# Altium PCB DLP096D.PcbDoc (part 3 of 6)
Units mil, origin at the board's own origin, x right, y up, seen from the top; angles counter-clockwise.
Board outline 4950 x 3159.45 mil, 8 copper layers (Top Layer, GND1, SIGNAL1, POWER1, POWER2, SIGNAL2, GND2, Bottom Layer), stack 60.4 mil thick; 328 components, 223 nets, 1380 pads, 856 vias.
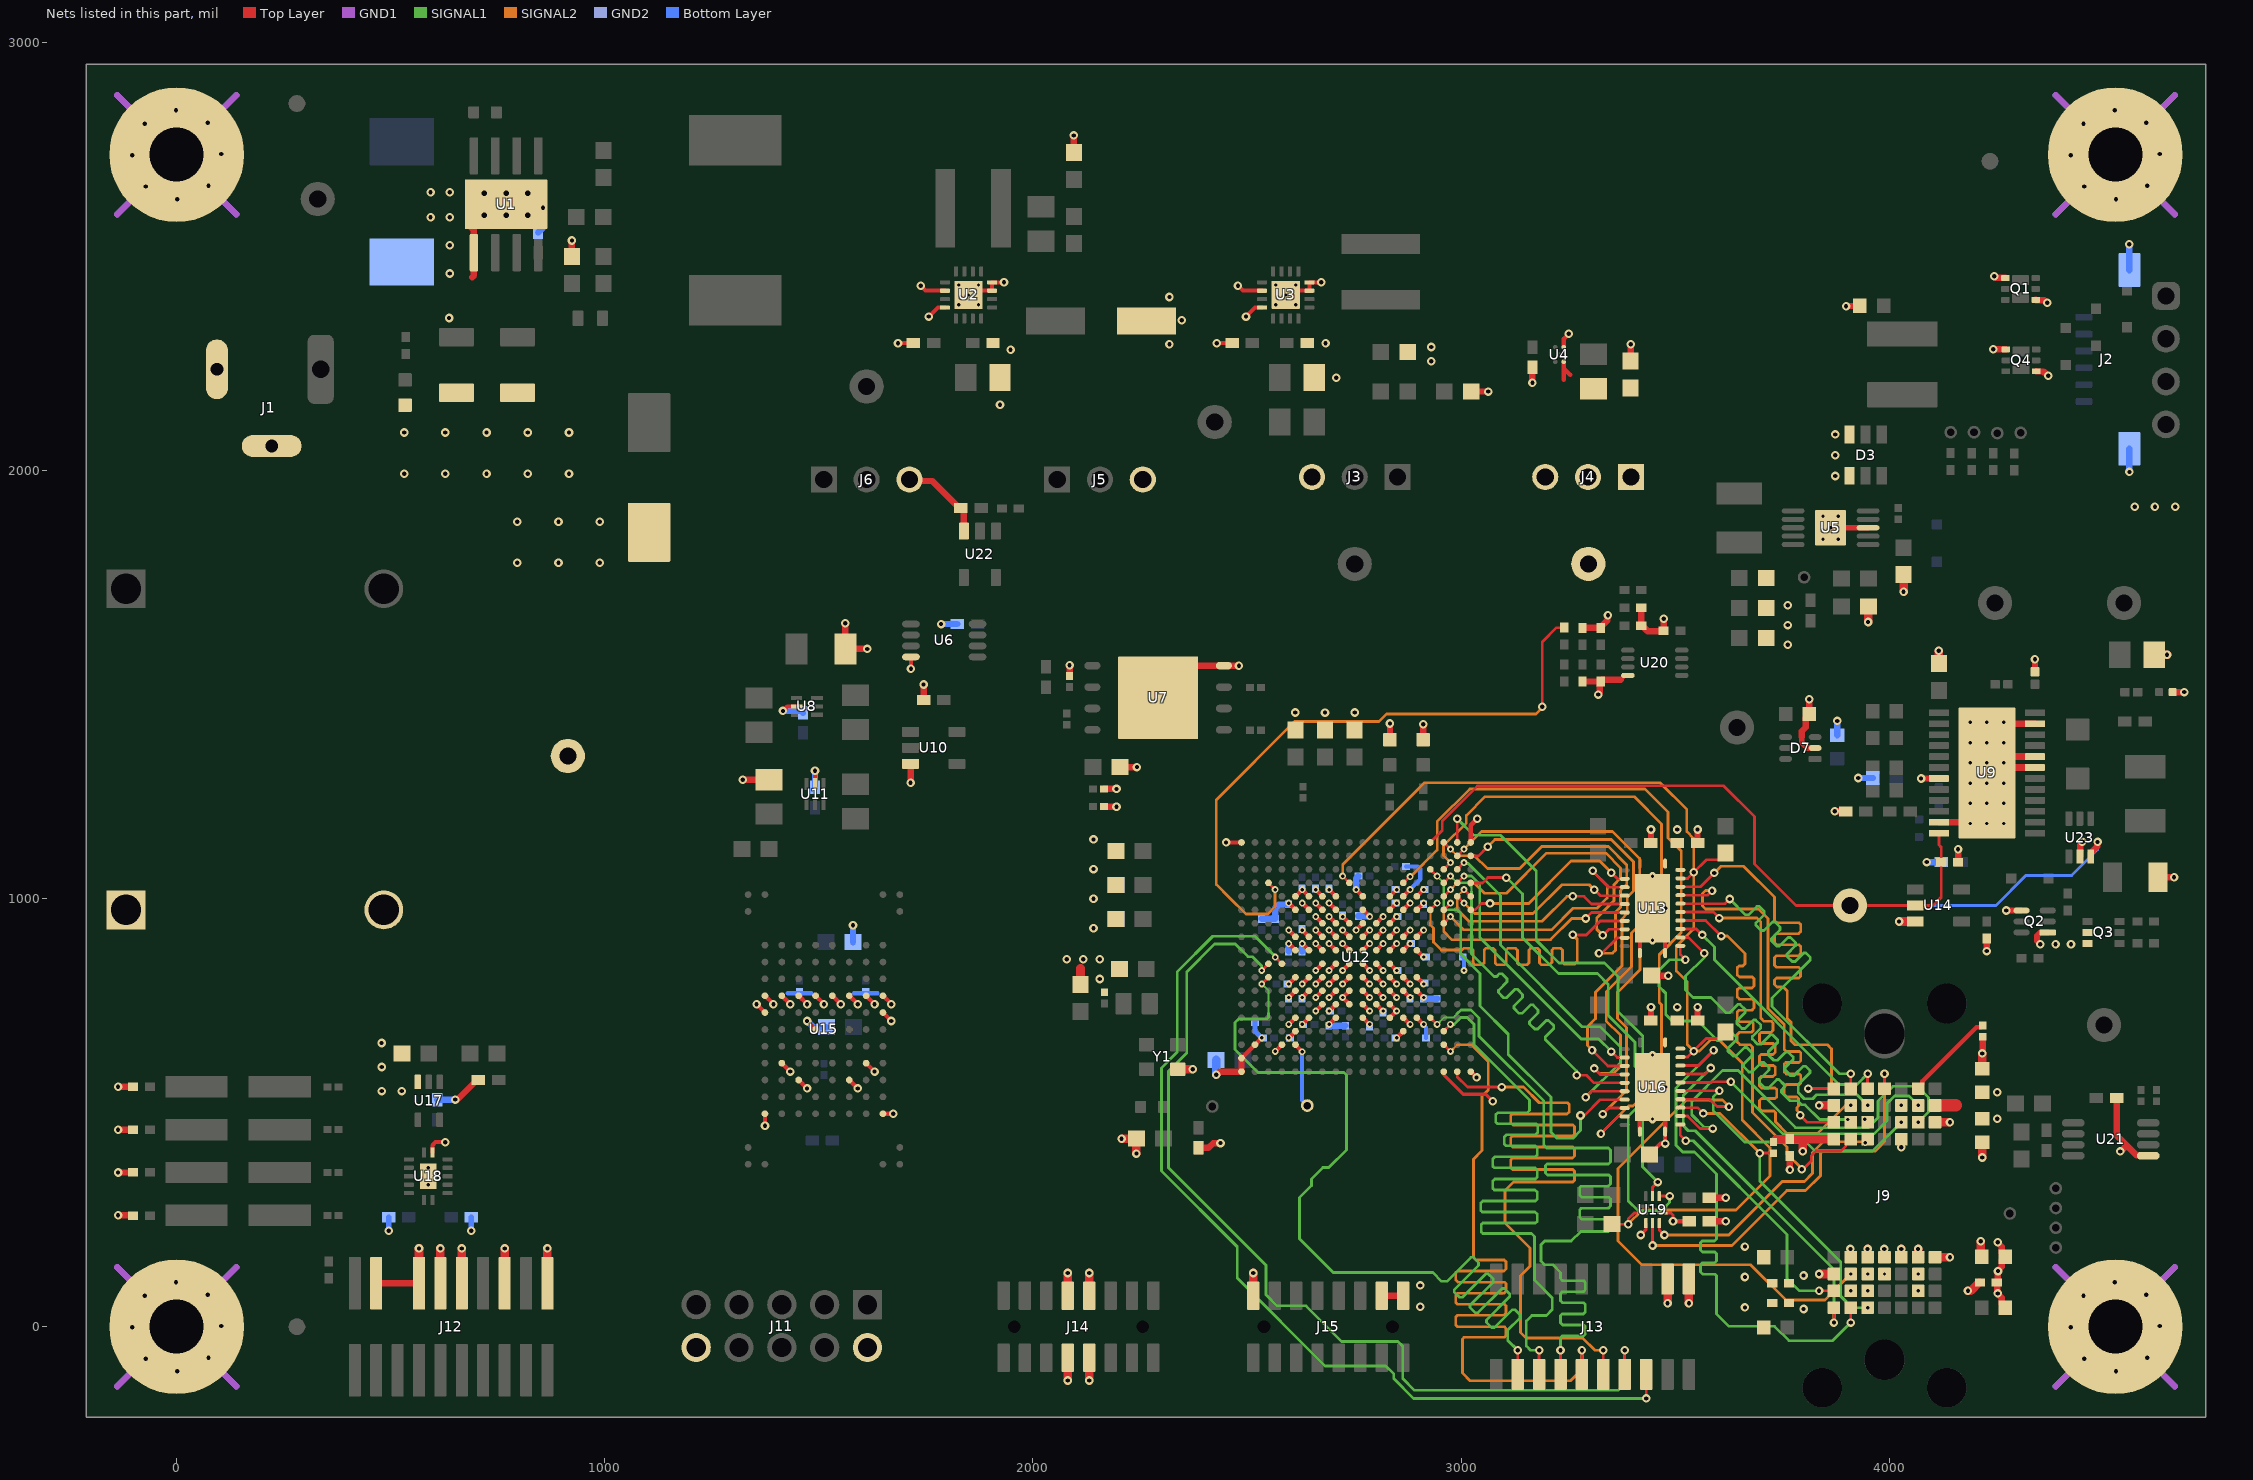
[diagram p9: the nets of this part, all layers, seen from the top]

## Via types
v1: diameter 20, hole 10, Top Layer to Bottom Layer, tented top, 596 vias
v2: diameter 16, hole 8, Top Layer to Bottom Layer, tented both sides, 126 vias
v3: diameter 16, hole 8.01, Top Layer to Bottom Layer, tented top, 63 vias
v4: diameter 19.68, hole 7.87, Top Layer to Bottom Layer, 37 vias
v5: diameter 16, hole 8.02, Top Layer to Bottom Layer, tented bottom, 22 vias
v6: diameter 24.8, hole 12.99, Top Layer to Bottom Layer, 6 vias
v7: diameter 19.68, hole 7.87, Top Layer to Bottom Layer, tented both sides, 6 vias

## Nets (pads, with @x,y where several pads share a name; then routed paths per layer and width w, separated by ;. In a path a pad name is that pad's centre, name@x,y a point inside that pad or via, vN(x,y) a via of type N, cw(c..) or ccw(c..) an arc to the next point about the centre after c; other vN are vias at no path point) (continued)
DAC_OUT: TP23.1 U12.T5 | length 153.6
  Top Layer w6.5: U12.T5@2613.07,658.27 U12.T5@2613.07,658.72 ; v3(2628.55,642.35) v3@2628.55,642.8
  Top Layer w10: U12.T5@2613.07,658.27 v3@2628.55,642.8
  Bottom Layer w10: v3(2628.55,642.35) 2628.55,528.65 TP23.1@2640.68,516.52
DMD_1V8: C42.2 C50.2 C52.1 C53.1 C55.1 C57.2 C58.1 C60.1 C61.1 C62.1 J4.2 J9.A5 J9.B12 J9.C14 J9.D12 J9.F13 J9.G3 R65.2 TP7.1 U13.23 U13.24 U16.23 U16.24 U19.6 | length 417.8
  Top Layer w7: U19.6@3470.73,265.67 3490.4,265.67 3494.93,261.15 v1(3494.93,246.28)
  Top Layer w10: v1(3494.93,246.28) C57.2@3532.29,246.28 ; v1@3909.25,184.4 3909.7,183.95 3909.7,162.92 J9.B12@3910.15,162.48 ; v1@3988.59,184.55 3988.74,184.4 3988.74,162.62 J9.D12@3988.89,162.48
  Top Layer w19.68: R65.2@3729.99,432.16 3735.9,438.07 C55.1@3767.94,438.07 3794.97,438.07 ; v1(3797.71,409.67) v1(3797.71,409.67) 3797.65,435.38 3794.97,438.07 ; J9.A5@3871.02,438.07 J9.A5@3870.78,438.07 3794.97,438.07 ; v1(4183.78,84.03) 4183.84,84.09 4190.74,84.09 4209.83,103.18 C60.1@4211.8,103.18 ; v1(4213.99,199.64) 4214.05,199.58 4214.05,164.73 C58.1@4215.74,163.04
  Top Layer w29: J9.G3@4107,516.81 4155.75,516.81
  other v1: 3799.96,41.32 3799.96,119.53 3909.25,181.73 3988.59,181.73 4252.41,485.92 4252.41,547.57 3504.97,746.65 3504.97,1161.3
  other v5: 3949.52,83.74 4067.63,123.11
DMD_1V8_OB: C12.1 J4.1 L5.2 U4.C3 | length 63
  Top Layer w10: 3239.65,2212.06 3239.65,2238.27 ; U4.C3@3239.65,2253.67 3239.65,2238.27 ; 3254.78,2223.14 3239.65,2238.27
DMD_D0: U12.F18 U13.3 | length 423.8
  Top Layer w6.5: U12.F18@3022.52,973.68 3032.3,973.68 3047.17,988.55 v1(3067.46,988.55) ; v1(3350.94,1060.17) 3364.93,1046.19 U13.3@3382.11,1046.19
  SIGNAL2 w6.5: v1(3067.46,988.55) 3073.74,988.55 3158.08,988.55 3256.96,1087.43 3323.69,1087.43 v1(3350.94,1060.17)
DMD_D0_1v8: J9.A2 U13.21 | length 1267.1
  Top Layer w6.5: U13.21@3512.03,1027.49 3558.88,1027.49 v1(3591.2,1059.81) ; v1(3811.01,556.18) J9.A2@3870.78,556.18
  SIGNAL2 w6.5: v1(3591.2,1059.81) 3606.95,1075.56 3659.95,1075.56 3732.17,1003.34 3732.17,948.49 3737.16,943.49 3789.25,943.49 3793.06,939.69 3793.06,922.71 3788.07,917.72 3735.98,917.72 3732.17,913.92 3732.17,896.94 3737.16,891.95 3789.25,891.95 3793.06,888.14 3793.06,871.17 3788.07,866.18 3735.98,866.18 3732.17,862.37 3732.17,844.35 3737.16,839.36 3788.75,839.36 3792.56,835.55 3792.56,818.57 3788.75,814.77 3737.16,814.77 3732.17,809.78 3732.17,799.64 3738.23,793.58 3752.38,793.58 3761.73,784.24 3761.73,720.15 3770.29,711.59 3770.29,667.91 3779.58,658.61 3855.35,658.61 3864.95,649.01 3864.95,564.41 3856.72,556.18 v1(3811.01,556.18)
DMD_D1: U12.G16 U13.4 | length 599.9
  Top Layer w6.5: U12.G16@2959.53,942.18 v2(2975.27,957.93) ; v1@3306.94,1064.49 3344.93,1026.5 U13.4@3382.11,1026.5
  SIGNAL2 w6.5: v2(2975.27,957.93) 3006.19,927.01 3210.71,927.01 3261.16,977.47 3317.1,977.47 3341.18,1001.55 3341.18,1030.25 v1@3306.94,1064.49
  other v1: 3307.16,1064.71
DMD_D1_1v8: J9.A4 U13.20 | length 1026.5
  Top Layer w6.5: U13.20@3512.03,1007.8 3575.47,1007.8 v1(3586.18,1018.51) ; v1(3791.81,493.73) 3808.1,477.44 3811.01,477.44 J9.A4@3870.78,477.44
  SIGNAL2 w6.5: v1(3586.18,1018.51) 3570.52,1018.51 3563.75,1011.73 3563.75,982.38 3570.55,975.57 3694.54,975.57 3716.49,953.63 3716.49,743.56 3754.63,705.42 3754.63,647.73 3759.62,642.74 3789.71,642.74 3793.51,638.94 3793.51,621.96 3788.52,616.97 3758.44,616.97 3754.63,613.16 3754.63,595.14 3759.62,590.15 3789.71,590.15 3793.51,586.34 3793.51,569.37 3789.71,565.56 3759.62,565.56 3754.63,560.57 3754.63,542.54 3760.73,536.44 3784.28,536.44 3788.09,532.64 3788.09,515.66 3784.28,511.86 3784.28,504.92 3791.81,497.38 v1(3791.81,493.73)
DMD_D2: U12.E17 U13.5 | length 446.3
  Top Layer w6.5: U12.E17@2991.02,1005.17 v2(3006.77,989.43) ; v1(3310.94,1020.8) 3324.93,1006.82 U13.5@3382.11,1006.82
  SIGNAL2 w6.5: v2(3006.77,989.43) 3031.29,964.91 3167.95,964.91 3235.41,1032.37 3299.38,1032.37 v1(3310.94,1020.8)
DMD_D2_1v8: J9.B2 U13.19 | length 1006.7
  Top Layer w6.5: U13.19@3512.03,988.12 3616.65,988.12 v1(3627.55,999.01) ; J9.B2@3910.15,556.18 v1(3910.15,590.94)
  SIGNAL1 w6.5: v1(3627.55,999.01) 3664.54,962.02 3671.02,962.02 3690.88,981.88 3696.27,981.88 3708.27,969.88 3708.27,962.82 3688.41,942.96 3688.41,937.57 3700.41,925.57 3707.47,925.57 3727.33,945.43 3732.71,945.43 3744.71,933.43 3744.71,926.37 3724.85,906.51 3724.85,901.13 3736.86,889.12 3743.91,889.12 3763.77,908.98 3769.16,908.98 3781.16,896.98 3781.16,889.93 3761.3,870.06 3761.3,864.68 3773.3,852.68 3780.36,852.68 3800.22,872.54 3805.61,872.54 3815.7,862.45 3815.7,857.06 3726.21,767.57 3726.21,748.34 3883.6,590.94 v1(3910.15,590.94)
DMD_D3: U12.E18 U13.6 | length 509.3
  Top Layer w6.5: v2(3006.77,1020.92) U12.E18@3022.52,1005.17 ; v1(3260.97,1005.15) 3286.91,1005.15 3304.93,987.13 U13.6@3382.11,987.13
  SIGNAL2 w5: 2994.72,970.45 2991.05,974.12 2991.05,1005.21 v2(3006.77,1020.92)
  SIGNAL2 w6.5: 2994.72,970.45 3018.06,947.11 3189.25,947.11 3247.29,1005.15 v1(3260.97,1005.15)
DMD_D3_1v8: J9.B3 U13.18 | length 1156.6
  Top Layer w6.5: U13.18@3512.03,968.43 3589.21,968.43 v1(3603.19,954.45)
  SIGNAL2 w6.5: v1(3603.19,954.45) 3691.01,954.45 3700.08,945.38 3700.08,720.51 3707.4,713.19 3724.72,713.19 3728.53,709.39 3728.53,692.41 3723.54,687.42 3700.45,687.42 3696.64,683.61 3696.64,666.64 3701.64,661.65 3729.72,661.65 3733.53,657.84 3733.53,640.87 3728.54,635.88 3700.45,635.88 3696.64,632.07 3696.64,615.1 3701.64,610.11 3729.72,610.11 3733.53,606.3 3733.53,589.33 3728.54,584.33 3700.45,584.33 3696.64,580.53 3696.64,562.5 3701.64,557.51 3733.22,557.51 3737.03,553.7 3737.03,536.73 3733.22,532.92 3701.64,532.92 3696.64,527.93 3696.64,509.91 3702.74,503.81 3730.29,503.81 3734.1,500 3734.1,478.68 3761.51,451.27 3832.47,451.27 3898,516.81 v5(3910.15,516.81)
DMD_D4: U12.F16 U13.7 | length 552.2
  Top Layer w6.5: U12.F16@2959.53,973.68 v2(2975.27,989.43) ; v1(3290.94,953.47) 3304.93,967.45 U13.7@3382.11,967.45
  SIGNAL2 w5: 2959.6,953.66 2959.6,973.75 v2(2975.27,989.43)
  SIGNAL2 w6.5: 2959.6,953.66 2959.6,922.37 2977.93,904.04 3208.87,904.04 3258.29,953.47 v1(3290.94,953.47)
DMD_D4_1v8: J9.B5 U13.17 | length 1128.7
  Top Layer w6.5: U13.17@3512.03,948.75 3571.16,948.75 v1(3607.59,912.32) ; v1(3795.87,367.65) 3798.11,367.65 3817.95,387.49 3817.95,399.38 3829.18,410.61 3887.45,410.61 3898.63,421.79 3898.63,426.55 J9.B5@3910.15,438.07
  SIGNAL2 w6.5: v1(3607.59,912.32) 3607.68,912.23 3622.44,912.23 3663.2,871.46 3663.2,847.83 3657.7,842.33 3648.78,842.33 3644.97,838.52 3644.97,821.55 3649.96,816.56 3680.05,816.56 3683.86,812.75 3683.86,795.78 3678.87,790.79 3648.78,790.79 3644.97,786.98 3644.97,770.01 3649.96,765.02 3680.05,765.02 3683.86,761.21 3683.86,744.23 3678.87,739.24 3648.78,739.24 3644.97,735.44 3644.97,717.41 3649.96,712.42 3678.55,712.42 3682.36,708.61 3682.36,691.64 3678.55,687.83 3649.96,687.83 3644.97,682.84 3644.97,664.81 3651.07,658.72 3674.62,658.72 3680.51,652.83 3680.51,500.47 3761.26,419.72 3761.26,403.44 3795.87,368.83 v1(3795.87,367.65)
DMD_D5: U12.F15 U13.8 | length 972.8
  Top Layer w6.5: U12.F15@2928.03,973.68 v2(2943.78,989.43) ; v1(3260.97,915.15) 3292.31,915.15 3324.93,947.76 U13.8@3382.11,947.76
  SIGNAL2 w5: 2928.1,944.54 2928.1,973.75 v2(2943.78,989.43)
  SIGNAL2 w6.5: 2928.1,944.54 2928.1,938.57 2935.3,931.37 2935.3,898.18 2953.79,879.69 3001.99,879.69 3006.4,884.11 3023.37,884.11 3028.36,879.11 3028.36,849.03 3032.17,845.22 3049.15,845.22 3054.14,850.21 3054.14,880.3 3057.94,884.11 3074.92,884.11 3079.91,879.11 3079.91,849.03 3083.72,845.22 3100.69,845.22 3105.68,850.21 3105.68,880.3 3109.49,884.11 3126.46,884.11 3131.45,879.11 3131.45,849.03 3135.26,845.22 3153.28,845.22 3158.28,850.21 3158.28,879.9 3162.08,883.71 3179.06,883.71 3182.86,879.9 3182.86,850.21 3187.86,845.22 3205.88,845.22 3211.98,851.32 3211.98,879.9 3215.79,883.71 3232.76,883.71 3236.57,879.9 3236.57,851.32 3241.56,846.33 3265.17,846.33 3271.17,852.32 3271.17,904.95 v1(3260.97,915.15)
DMD_D5_1v8: J9.C2 U13.16 | length 650.3
  Top Layer w6.5: U13.16@3512.03,929.06 3549.21,929.06 v1(3563.19,915.08) ; J9.C2@3949.52,556.18 v1(3949.52,590.94)
  SIGNAL1 w6.5: v1(3563.19,915.08) 3591.78,886.49 3591.78,857.05 3882.91,565.91 3924.49,565.91 v1(3949.52,590.94)
DMD_D6: U12.E16 U13.9 | length 732.7
  Top Layer w6.5: U12.E16@2959.53,1005.17 v2(2975.27,1020.92) ; v1(3330.94,914.1) 3344.93,928.08 U13.9@3382.11,928.08
  SIGNAL2 w5: v2(2975.27,1020.92) 2991.06,1036.71 3016.27,1036.71
  SIGNAL2 w6.5: 3016.27,1036.71 3030.34,1036.71 3054.73,1012.33 3054.79,1012.33 3105.91,1012.33 3199.6,1106.01 3338.16,1106.01 3372.53,1071.64 3372.53,1047.94 3356.92,1032.33 3356.92,994.95 3316.7,954.73 3316.7,928.34 v1(3330.94,914.1)
DMD_D6_1v8: J9.C3 U13.15 | length 1065.3
  Top Layer w6.5: U13.15@3512.03,909.38 3530.77,909.38 v1(3568.07,872.07)
  SIGNAL1 w6.5: v1(3568.07,872.07) 3568.07,862.76 3524.06,818.74 3524.06,786.17 3541.53,768.7 3583.7,768.7 3619.27,733.13 3626.32,733.13 3646.19,752.99 3651.57,752.99 3663.57,740.99 3663.57,733.93 3643.71,714.07 3643.71,708.69 3655.71,696.69 3662.77,696.69 3682.63,716.55 3688.02,716.55 3700.02,704.55 3700.02,697.49 3680.16,677.63 3680.16,672.24 3692.9,659.5 3699.96,659.5 3722.3,681.83 3727.68,681.83 3739.68,669.83 3739.68,664.45 3717.35,642.11 3717.35,635.05 3730.09,622.3 3738.72,622.3 3758.2,641.79 3763.59,641.79 3775.59,629.78 3775.59,624.4 3757.12,605.94 3757.12,598.88 3769.87,586.13 3776.93,586.13 3799.26,608.47 3804.65,608.47 3814.65,598.47 3814.65,593.08 3787.47,565.91 3787.47,546.64 3801.55,532.56 3821.31,532.56 3830.43,541.68 3924.64,541.68 v5(3949.52,516.81)
DMD_D7: U12.A16 U13.10 | length 818.9
  Top Layer w6.5: U12.A16@2959.53,1131.16 v2(2975.27,1115.41) ; v1(3321.82,872.43) 3328.96,872.43 3364.93,908.39 U13.10@3382.11,908.39
  SIGNAL2 w5: v2(2975.27,1115.41) 2990.82,1099.86 3014.15,1099.86
  SIGNAL2 w6.5: 3014.15,1099.86 3031.5,1099.86 3061.34,1070.02 3137.01,1070.02 3188.32,1121.32 3344.38,1121.32 3386.9,1078.81 3386.9,1033.25 3372.43,1018.77 3372.43,979.77 3360.85,968.19 3360.85,879.31 3353.97,872.43 v1(3321.82,872.43)
DMD_D7_1v8: J9.B4 U13.14 | length 980.3
  Top Layer w6.5: U13.14@3512.03,889.69 3512.03,869.02 v1(3523.86,857.19)
  SIGNAL1 w6.5: v1(3523.86,857.19) 3486.51,857.19 3461.89,832.58 3461.89,794.97 3477.96,778.9 3477.96,728.83 3492.92,713.88 3553.06,713.88 3598.45,668.49 3605.5,668.49 3625.37,688.35 3630.75,688.35 3642.75,676.35 3642.75,669.29 3622.89,649.43 3622.89,644.05 3634.89,632.04 3641.95,632.04 3661.81,651.9 3667.2,651.9 3679.2,639.9 3679.2,632.84 3659.34,612.98 3659.34,607.6 3672.08,594.85 3679.14,594.85 3701.48,617.19 3706.86,617.19 3718.86,605.19 3718.86,599.8 3696.53,577.47 3696.53,570.41 3709.27,557.66 3717.9,557.66 3737.38,577.14 3742.77,577.14 3754.77,565.14 3754.77,559.76 3748.05,553.04 3748.05,547.65 3767.7,528 3785.78,528 3795.6,518.18 3803.5,518.18 3837.66,484.02 v5(3903.56,484.02)
DMD_D8: U12.D18 U19.8 | length 1208.2
  Top Layer w6.5: U12.D18@3022.52,1036.67 3050.23,1036.67 3062.45,1048.89 v1(3105.67,1048.89) ; U19.8@3462.85,305.04 v1(3487,305.04)
  SIGNAL1 w6.5: v1(3105.67,1048.89) 3143.48,1011.09 3143.48,908.48 3227.31,824.65 3318.53,824.65 3343.67,799.51 3343.67,726.89 3406.28,664.28 3406.28,607.68 3439.75,574.21 3439.75,540.78 3390.24,491.28 3390.24,294.14 3413.04,271.34 3467.99,271.34 3487,290.35 v1(3487,305.04)
DMD_D8_1v8: J9.C5 U19.5 | length 636.8
  Top Layer w6.5: U19.5@3462.85,242.05 3462.85,226.3 v1(3474.94,214.22) ; J9.C5@3938,426.55 J9.C5@3949.52,438.07
  SIGNAL2 w6.5: v1(3474.94,214.22) 3625.17,214.22 3750.16,339.21 3801.68,339.21 3820.9,358.43 3820.9,406.72 3846.32,432.14 v5@3944.08,432.14
  other v5: 3944.08,429.6
DMD_D9: U12.A17 U19.9 | length 1259.8
  Top Layer w6.5: U12.A17@2991.02,1131.16 v1(2991.02,1186.35) ; U19.9@3447.11,305.04 3447.11,325.79 v1(3459.19,337.87)
  SIGNAL1 w6.5: v1(2991.02,1186.35) 3029.68,1147.69 3092.45,1147.69 3175.48,1064.66 3175.48,902.54 3228.62,849.4 3334.8,849.4 3366.61,817.59 3366.61,736.32 3424.5,678.43 3424.5,619.08 3454.12,589.46 3454.12,534.83 3423.43,504.14 3423.43,373.62 v1(3459.19,337.87)
DMD_D9_1v8: J9.D2 U19.4 | length 919.3
  Top Layer w6.5: v1(3447.11,189.62) U19.4@3447.11,242.05 ; J9.D2@3988.89,556.18 v1(3988.89,590.94)
  SIGNAL2 w6.5: v1(3447.11,189.62) 3632.37,189.62 3760.83,318.08 3804.62,318.08 3839.09,352.56 3839.09,404.59 3844.77,410.26 3967.95,410.26 3988.89,431.2 v1(3988.89,590.94)
DMD_DAD_BUS: U12.D17 U16.3 | length 645.4
  Top Layer w6.5: U12.D17@2991.02,1036.67 v2(3006.77,1052.42) ; v1(3350.94,642.68) 3364.93,628.7 U16.3@3382.11,628.7
  SIGNAL1 w6.5: v2(3006.77,1052.42) 3023.85,1052.42 3043.66,1032.62 3043.66,909.18 3280.7,672.14 3321.49,672.14 v1(3350.94,642.68)
DMD_DAD_BUS_1v8: J9.B15 U16.21 | length 1318.1
  Top Layer w6.5: U16.21@3512.03,610 3554.27,610 v1(3589.67,645.39) ; v1(3910.15,9.6) J9.B15@3910.15,44.37
  SIGNAL1 w6.5: v1(3589.67,645.39) 3501.86,557.58 3501.86,423.74 3517.77,407.83 3544.85,407.83 3596.22,356.46 3596.22,205 3591.23,200.01 3563.14,200.01 3559.34,196.2 3559.34,179.23 3564.33,174.24 3592.42,174.24 3596.22,170.43 3596.22,153.46 3591.23,148.47 3563.14,148.47 3559.34,144.66 3559.34,127.69 3564.33,122.7 3592.42,122.7 3596.22,118.89 3596.22,29.92 3625.31,0.83 3732.16,0.83 3765.55,-32.56 3867.98,-32.56 v1(3910.15,9.6)
DMD_DCLK: U12.C16 U16.9 | length 1470.5
  Top Layer w6.5: U12.C16@2959.53,1068.17 v2(2975.27,1083.91) ; v1(3330.94,496.6) 3344.93,510.59 U16.9@3382.11,510.59
  SIGNAL2 w6.5: v2(2975.27,1083.91) 2959.02,1100.16 2959.02,1123.73 3012.15,1176.85 3012.15,1194.05 3056.13,1238.03 3404.27,1238.03 3468.03,1174.27 3468.03,1008.25 3452.01,992.23 3452.01,952.49 3418.08,918.55 3418.08,833.69 3365.41,781.02 3365.41,719.8 3386.44,698.77 3386.44,552.1 v1(3330.94,496.6)
DMD_DCLK_1v8: J9.F4 U16.15 | length 961.1
  Top Layer w6.5: U16.15@3512.03,491.89 3529.21,491.89 3558.26,462.83 v1(3587.82,462.83)
  SIGNAL1 w6.5: v1(3587.82,462.83) 3585.23,465.42 3568.35,465.42 3538.76,495 3538.76,526.3 3610.86,598.4 3647.2,598.4 3780.7,464.9 3950.62,464.9 3973.89,488.17 3973.89,526.77 4008.52,561.39 4066.05,561.39 4091.77,535.67 4091.77,501.58 v5(4067.63,477.44)
DMD_INTERFACE_EN: R35.2 R45.2 R72.2 U12.D9 U13.22 U16.22 U19.2 | length 2727.7
  Top Layer w6.5: v2(2723.3,1052.42) U12.D9@2739.05,1036.67 ; R72.2@3352.82,239.44 v1(3390.19,239.44) 3390.19,251.59 3404.27,265.67 U19.2@3423.48,265.67 ; U16.22@3512.03,629.68 3529.21,629.68 v1(3543.19,643.66) 3572.47,672.94 3603.07,672.94 R45.2@3617.77,687.65 ; U13.22@3512.03,1047.17 3529.21,1047.17 v1(3543.19,1061.15) 3572.47,1090.44 3603.07,1090.44 3617.77,1105.14 R35.2@3617.77,1106.01
  SIGNAL2 w6.5: v2(2723.3,1052.42) 2723.3,1078.89 2914.92,1270.5 3464.58,1270.5 3527.16,1207.91 3527.16,1156.48 3543.19,1140.45 v1(3543.19,1061.15) 3543.19,928.95 3502.74,888.49 3502.74,830.96 3528.32,805.37 3528.32,658.53 v1(3543.19,643.66) 3556.69,643.66 3583.73,670.71 3601.89,670.71 3656.58,616.01 3656.58,483.01 3721.79,417.8 3721.79,352.17 3642.15,272.53 3423.27,272.53 v1(3390.19,239.44)
DMD_LOADB: U12.B17 U16.5 | length 1174.5
  Top Layer w6.5: U12.B17@2991.02,1099.66 v2(3006.77,1115.41) ; v1(3310.94,603.31) 3324.93,589.33 U16.5@3382.11,589.33
  SIGNAL2 w6.5: v2(3006.77,1115.41) 3047.99,1156.63 3353.75,1156.63 3417.08,1093.3 3417.08,1018.11 3437.52,997.67 3437.52,958.78 3397.99,919.24 3397.99,840.6 3338.76,781.37 3338.76,714.38 3372.07,681.07 3372.07,607.88 3355.4,591.21 3323.04,591.21 v1(3310.94,603.31)
DMD_LOADB_1v8: J9.F3 U16.19 | length 675.8
  Top Layer w6.5: U16.19@3512.03,570.63 3584.84,570.63 3586.28,572.06 3612.19,572.06 3612.31,571.94 v1(3630.19,571.94)
  SIGNAL1 w6.5: v1(3630.19,571.94) 3751.6,450.52 3964.27,450.52 3995.28,481.53 3995.28,521.93 4012.04,538.69 4045.75,538.69 v5(4067.63,516.81)
DMD_POWER_EN: R37.2 TP11.1 U9.24 U12.A15 U14.2 U23.3 | length 2292.3
  Top Layer w6.5: U12.A15@2928.03,1131.16 2956.04,1159.16 2956.04,1181.24 3038.14,1263.34 3613.47,1263.34 3685.12,1191.69 3685.12,1080.97 3782.21,983.88 TP11.1@3908.42,983.88 U14.2@4060.65,983.88 4102.23,983.88 4121.44,1003.08 R37.2@4121.44,1085.17 4121.44,1119.9 4115.92,1125.41 U9.24@4115.92,1152.54
  Top Layer w15: U23.3@4470.88,1098.19 4470.88,1107.05 4485.61,1121.78 4485.61,1131.37 v1(4486.56,1132.33)
  Bottom Layer w6.5: TP11.1@3908.42,983.88 4249.1,983.88 4318.91,1053.69 4426.08,1053.69 4486.56,1114.18 v1(4486.56,1132.33)
DMD_RESET_OEZ: U12.C15 U16.8 | length 980
  Top Layer w6.5: U12.C15@2928.03,1068.17 v2(2943.78,1052.42) ; v1(3278.89,493.24) 3287.89,493.24 3324.93,530.27 U16.8@3382.11,530.27
  SIGNAL1 w5: v2@2943.78,1052.34 2959.51,1036.61 2959.51,983.27 2968.85,973.93 2984.25,973.93
  SIGNAL1 w6.5: 2984.25,973.93 2991.52,973.93 2999.06,966.39 2999.06,870.21 3044.42,824.86 3044.42,748.76 3109.98,683.19 3109.98,636.18 3209.95,536.21 3209.95,454.25 3224.16,440.04 3260.94,440.04 3278.89,457.99 v1(3278.89,493.24)
DMD_RESET_OEZ_1v8: J9.C15 R65.1 U16.16 | length 748.3
  Top Layer w6.5: U16.16@3512.03,511.57 3552.07,511.57 v1(3565.54,498.1) ; v1(3697.39,405.39) R65.1@3729.21,405.39
  SIGNAL1 w6.5: v1(3697.39,405.39) 3697.39,340.15 3886.6,150.95 3886.6,71.17 3913.7,44.07 v5(3949.9,44.07)
  SIGNAL2 w6.5: v1(3565.54,498.1) 3604.69,498.1 v1(3697.39,405.39)
DMD_RESET_STROBE: U12.C17 U16.7 | length 881.7
  Top Layer w6.5: U12.C17@2991.02,1068.17 v2(3006.77,1083.91) ; v1(3290.94,535.97) 3304.93,549.96 U16.7@3382.11,549.96
  SIGNAL1 w6.5: v2(3006.77,1083.91) 3008.59,1082.1 3016.71,1082.1 3091.72,1007.09 3091.72,891.56 3282.82,700.46 3325.18,700.46 3372.07,653.57 3372.07,617.1 v1(3290.94,535.97)
DMD_RESET_STROBE_1v8: J9.B13 U16.17 | length 1246.8
  Top Layer w6.5: U16.17@3512.03,531.26 3580.17,531.26 3597.38,514.04 v1(3625.46,514.04)
  SIGNAL2 w6.5: v1(3625.46,514.04) 3610.2,529.3 3526.52,529.3 3366.51,369.28 3366.51,200.39 3422.36,144.55 3676.59,144.55 3758.53,62.61 3849.65,62.61 v5(3910.15,123.11)
DMD_SAC_BUS: U12.B18 U16.4 | length 997.8
  Top Layer w6.5: U12.B18@3022.52,1099.66 3040.48,1099.66 v1(3061.96,1121.14) ; v1(3305.8,645.94) 3342.73,609.01 U16.4@3382.11,609.01
  SIGNAL2 w6.5: v1(3061.96,1121.14) 3078.71,1137.89 3350.59,1137.89 3402.39,1086.09 3402.39,1017.39 3387.87,1002.87 3387.87,964.77 3375.68,952.58 3375.68,843.14 3313.85,781.3 3313.85,719.47 3295.05,700.68 3295.05,656.69 v1(3305.8,645.94)
DMD_SAC_BUS_1v8: J9.A15 U16.20 | length 888.5
  Top Layer w6.5: U16.20@3512.03,590.31 3569.21,590.31 v1(3583.19,604.29) ; v1(3870.78,9.6) J9.A15@3870.78,44.37
  SIGNAL1 w6.5: v1(3583.19,604.29) 3518.77,539.87 3518.77,469.5 3530.58,457.69 3546.95,457.69 3870.78,133.87 v1(3870.78,9.6)
DMD_SAC_CLK: U12.D13 U16.10 | length 1695.2
  Top Layer w6.5: U12.D13@2865.04,1036.67 2865.63,1036.67 2880.35,1051.39 v2(2880.94,1051.39) ; v1(3326.52,450.91) 3366.51,490.9 U16.10@3382.11,490.9
  SIGNAL2 w6.5: v2(2880.94,1051.39) 2882.27,1051.39 2944.13,1113.26 2944.13,1179.9 3020.36,1256.13 3429.19,1256.13 3483.36,1201.95 3483.36,1141.74 3514.25,1110.85 3514.25,920.34 3462.66,868.75 3462.66,757.34 3468.03,751.97 3468.03,581.63 3401.72,515.31 3390.91,515.31 v1(3326.52,450.91)
DMD_SAC_CLK_1v8: J9.A14 U16.14 | length 594.6
  Top Layer w6.5: U16.14@3512.03,472.2 3512.03,446.96 v1(3524.71,434.28) ; v1(3836.01,83.74) J9.A14@3870.78,83.74
  SIGNAL1 w6.5: v1(3524.71,434.28) 3542.25,434.28 3761.42,215.11 3761.42,112.38 3790.06,83.74 v1(3836.01,83.74)
DMD_SCTRL: U12.D16 U16.6 | length 969.5
  Top Layer w6.5: U12.D16@2959.53,1036.67 v2(2975.27,1052.42) ; v1(3269.89,587.54) 3292.29,587.54 3310.18,569.64 U16.6@3382.11,569.64
  SIGNAL1 w5: v2(2975.27,1052.42) 2990.77,1036.92 3014.56,1036.92 3024.4,1027.07 3024.4,1016.02
  SIGNAL1 w6.5: 3024.4,1016.02 3024.4,870.39 3076.61,818.18 3083.13,818.18 3089.58,824.63 3094.97,824.63 3106.97,812.63 3106.97,805.57 3087.11,785.71 3087.11,780.32 3099.11,768.32 3106.17,768.32 3126.03,788.18 3131.41,788.18 3143.42,776.18 3143.42,769.12 3123.55,749.26 3123.55,743.88 3135.56,731.88 3142.61,731.88 3162.48,751.74 3167.86,751.74 3179.86,739.74 3179.86,732.68 3160,712.82 3160,707.43 3172,695.43 3179.06,695.43 3198.92,715.29 3204.31,715.29 3216.31,703.29 3216.31,696.23 3196.45,676.37 3196.45,670.99 3269.89,597.54 v1(3269.89,587.54)
DMD_SCTRL_1v8: J9.E4 U16.18 | length 650.2
  Top Layer w6.5: U16.18@3512.03,550.94 v1(3603.44,550.94)
  SIGNAL1 w6.5: v1(3603.44,550.94) 3588.77,536.28 3588.77,504.58 3661.94,431.41 3805.85,431.41 3826.99,410.26 3961.08,410.26 v5(4028.26,477.44)
DMD_TRC_1v8: J9.F2 R82.2 | length 216.4
  Top Layer w10: J9.F2@4067.63,556.18 4077.39,565.94 4077.39,573.18 4203.64,699.43 4215.03,699.43 4218.3,702.7 R82.2@4218.3,703.48
G_LED_IADJ_PWM: R30.1 U12.D3 | length 1502.4
  Top Layer w6.5: U12.D3@2550.08,1036.48 v2@2565.42,1021.14 ; v1(3189.4,1448.06) 3189.4,1599.18 3222.97,1632.76 R30.1@3240.8,1632.76
  Top Layer w10: U12.D3@2550.08,1036.48 U12.D3@2550.08,1036.67 ; v2(2565.42,1020.95) v2@2565.42,1021.14
  SIGNAL2 w6.5: v2(2565.42,1020.95) 2565.42,981.09 2548.29,963.96 2497.27,963.96 2459.64,1001.59 2428.31,1032.92 2428.31,1230.7 2610.85,1413.24 2808.35,1413.24 2826.03,1430.93 3174.78,1430.93 v1@3191.83,1447.98
GND: C4.1 C5.1 C6.2 C7.2 C8.2 C9.2 C10.2 C11.2 C12.2 C13.2 C14.2 C15.2 C16.2 C18.2 C19.2 C20.2 C21.2 C22.2 C23.2 C24.2 C25.1 C26.2 C28.2 C30.2 C31.2 C32.2 C35.2 C36.2 C38.2 C39.1 C40.1 C41.2 C42.1 C43.2 C44.2 C45.2 C46.2 C47.2 C48.2 C49.2 C50.1 C51.2 C52.2 C53.2 C54.2 C55.2 C56.2 C57.1 C58.2 C59.2 C60.2 C61.2 C62.2 C63.2 C64.2 C65.2 C66.2 C68.2 C69.2 C70.2 C71.2 C501.2 C503.2 C504.2 C505.2 C506.2 C507.2 C508.2 C509.2 C510.2 C511.2 C512.2 C513.2 C514.2 C515.2 C516.2 C517.2 C518.2 C519.2 C520.2 C521.2 C522.2 C523.2 C524.2 C525.2 C526.2 C527.2 C528.2 C529.2 C530.2 C531.2 C532.2 C533.2 C534.2 C535.2 C536.2 C537.2 C538.2 C539.2 C540.2 C541.2 C542.2 C543.2 C544.2 C545.2 C546.2 C547.2 C548.2 C549.2 C550.2 C551.2 C552.2 C553.2 C554.2 C555.2 C556.2 C557.1 D2.1 D3.3 D3.4 D5.1 D6.1 D7.2 D500.2 H1.1 H2.1 H3.1 H4.1 J1.2 J1.3 J2.7 J2.8 J3.3 J4.3 J5.3 J6.3 J8.1 J8.2 J9.A3 J9.A13 J9.B14 J9.C4 J9.C12 J9.C13 J9.D13 J9.E3 J9.E5 J9.E12 J9.F12 J9.F14 J9.G4 J9.G12 J11.2 J11.10 J12.4 J12.8 J12.10 J12.12 J12.16 J12.20 J13.2 J13.4 J14.7 J14.8 J14.9 J14.10 J15.2 J15.4 J15.16 Q1.1 Q1.4 Q2.1 Q2.4 Q3.5 Q3.6 Q4.1 Q4.4 R2.1 R6.1 R8.1 R13.1 R15.1 R17.1 R18.1 R21.1 R27.1 R37.1 R39.1 R43.1 R48.1 R49.1 R51.1 R62.1 R64.1 R66.1 R68.1 R71.1 R73.2 R82.1 R500.1 TP17.1 U1.1 U1.9 U2.6 U2.8 U2.15 U2.16 U2.17@1849.56,2409.85 U3.6 U3.8 U3.15 U3.16 U3.17@2590.39,2409.85 U4.A3 U5.3 U5.11 U6.4 U7.4 U7.9 U8.2 U9.7 U9.8 U9.11 U9.19 U9.23 U9.25@4228.13,1293.29 U10.3 U11.5 U12.A1 U12.A18 U12.E5 U12.E6 U12.E7 U12.E8 U12.E10 U12.E12 U12.E13 U12.E14 U12.F5 U12.F6 U12.F7 U12.F8 U12.F10 U12.F12 U12.F13 U12.F14 U12.G7 U12.G8 U12.G9 U12.G10 U12.G11 U12.G12 U12.H5 U12.H6 U12.H7 U12.H8 U12.H9 U12.H10 U12.H11 U12.H12 U12.H13 U12.H14 U12.J5 U12.J6 U12.J7 U12.J8 U12.J9 U12.J10 U12.J11 U12.J12 U12.J13 U12.J14 U12.K7 U12.K8 U12.K9 U12.K10 U12.K11 U12.K12 U12.L5 U12.L6 U12.L7 U12.L8 U12.L9 U12.L10 U12.L11 U12.L12 U12.L13 U12.L14 U12.M5 U12.M6 U12.M7 U12.M8 U12.M9 U12.M10 U12.M11 U12.M12 U12.M13 U12.M14 U12.N7 U12.N8 U12.N9 U12.N10 U12.N11 U12.N12 U12.P5 U12.P6 U12.P8 U12.P10 U12.P12 U12.P13 U12.P14 U12.R5 U12.R13 U12.T2 U12.T4 U12.U1 U12.V1 U12.V16 U12.V18 U13.12 U13.13 U13.25 U14.3 U15.G2 U15.G3 U15.G4 U15.G5 U15.G6 U15.G7 U15.G8 U15.G9 U15.H2 U15.H9 U15.J5 U15.L3 U15.L8 U15.M4 U15.M7 U15.P2 U15.P9 U16.12 U16.13 U16.25 U17.3 U18.7 U18.15 U19.3 U20.4 U21.5 U22.3 U23.2 Y1.2 | length 16980.9
  Top Layer w7: v1(3419.28,214.22) 3431.36,226.3 U19.3@3431.36,242.05
  Top Layer w8: U12.V16@2959.53,595.73 2960.63,594.63 2960.63,587.39 3005.06,542.95 3057.3,542.95 v1(3073.74,526.51)
  Top Layer w9: U13.12@3417.54,872.96 3417.54,947.76 U13.25@3447.07,977.29 3476.6,947.76 U13.13@3476.6,872.96 ; R66.1@3440.1,402.55 3465.33,427.78 v1(3476.6,427.78) U16.13@3476.6,455.47
  Top Layer w9.4: v1(1684.81,2297.32) C6.2@1720.59,2297.32 ; v1(1737.85,2431.26) 1749.41,2419.69 U2.6@1794.44,2419.69 ; v1(1756.8,2359.35) 1777.77,2380.32 U2.8@1794.44,2380.32 ; v4(1849.56,2409.85) 1859.4,2419.69 U2.15@1904.68,2419.69 U2.16@1904.68,2439.38 v1(1932.31,2439.38) ; v1(2429.15,2297.27) C8.2@2464.93,2297.27 ; v1(2478.68,2431.26) 2490.24,2419.69 U3.6@2535.27,2419.69 ; v1(2497.63,2359.35) 2518.6,2380.32 U3.8@2535.27,2380.32 ; v4(2590.39,2409.85) 2600.23,2419.69 U3.15@2645.51,2419.69 U3.16@2645.51,2439.38 v1(2673.14,2439.38)
  Top Layer w9.8: U18.7@597.43,406.53 597.45,423.91 604.66,431.12 v1(627.42,431.12) ; v1@1415.8,1438.49 1426.09,1448.78 U8.2@1448.44,1448.8
  Top Layer w10: v1(1354.35,753.36) U15.H2@1374.03,733.67 ; v1(1374.03,469.61) U15.P2@1374.03,497.45 ; U15.G2@1374.03,773.04 v1(1393.72,753.36) ; U15.L3@1413.4,615.56 v1(1433.09,595.88) ; U15.G3@1413.4,773.04 v1(1433.09,753.36) ; U15.M4@1452.77,576.19 v1(1472.46,556.51) ; U15.G4@1452.77,773.04 v1(1472.46,753.36) ; v1(1472.46,713.99) U15.J5@1492.14,694.3 ; U11.5@1490.93,1267.34 v1(1490.93,1298.41) ; U15.G5@1492.14,773.04 v1(1511.83,753.36) ; U15.G6@1531.51,773.04 v1(1551.2,753.36) ; U15.M7@1570.88,576.19 v1(1590.57,556.51) ; U15.G7@1570.88,773.04 v1(1590.57,753.36) ; U15.L8@1610.25,615.56 v1(1629.94,595.88) ; U15.G8@1610.25,773.04 v1(1629.94,753.36) ; U15.P9@1649.62,497.45 v1(1673.5,497.45) ; U15.H9@1649.62,733.67 v1(1669.31,713.99) ; U15.G9@1649.62,773.04 v1(1669.31,753.36) ; v1(1715,1536.56) U6.4@1715,1564.44 ; v1(2451.02,1131.16) U12.A1@2487.08,1131.16 ; U12.U1@2487.08,627.22 U12.T2@2518.58,658.72 v3(2534.33,674.47) ; v2(2565.82,642.97) U12.T4@2581.57,658.72 ; v3(2597.32,674.47) U12.R5@2613.07,690.21 ; v2(2597.32,705.96) U12.P5@2613.07,721.71 ; v3(2597.32,768.95) U12.M5@2613.07,784.7 ; v3(2597.32,800.45) U12.L5@2613.07,816.2 ; v2(2597.32,894.94) U12.J5@2613.07,879.19 ; v2(2597.32,926.43) U12.H5@2613.07,910.69 ; v3(2597.32,989.43) U12.F5@2613.07,973.68 ; U12.E5@2613.07,1005.17 v3(2628.82,1020.92) U12.E6@2644.56,1005.17 ; v3(2628.82,705.96) U12.P6@2644.56,721.71 ; v3(2628.82,768.95) U12.M6@2644.56,784.7 ; v2(2628.82,800.45) U12.L6@2644.56,816.2 ; v2(2628.82,894.94) U12.J6@2644.56,879.19 ; v3(2628.82,926.43) U12.H6@2644.56,910.69 ; v2(2628.82,989.43) U12.F6@2644.56,973.68 ; v2(2660.31,737.46) U12.N7@2676.06,753.21 ; v2(2660.31,768.95) U12.M7@2676.06,784.7 ; v2(2660.31,800.45) U12.L7@2676.06,816.2 ; v2(2660.31,831.95) U12.K7@2676.06,847.69 ; v2(2660.31,894.94) U12.J7@2676.06,879.19 ; v2(2660.31,926.43) U12.H7@2676.06,910.69 ; v2(2660.31,957.93) U12.G7@2676.06,942.18 ; v2(2660.31,989.43) U12.F7@2676.06,973.68 ; v3(2660.31,1020.92) U12.E7@2676.06,1005.17 ; v3(2691.81,705.96) U12.P8@2707.56,721.71 ; v3(2691.81,737.46) U12.N8@2707.56,753.21 ; v2(2691.81,768.95) U12.M8@2707.56,784.7 ; v2(2691.81,800.45) U12.L8@2707.56,816.2 ; v2(2691.81,831.95) U12.K8@2707.56,847.69 ; v2(2691.81,894.94) U12.J8@2707.56,879.19 ; v2(2691.81,926.43) U12.H8@2707.56,910.69 ; v2(2691.81,957.93) U12.G8@2707.56,942.18 ; v2(2691.81,989.43) U12.F8@2707.56,973.68 ; v3(2691.81,1020.92) U12.E8@2707.56,1005.17 ; v2(2723.3,800.45) U12.L9@2739.05,816.2 ; v2(2723.3,831.95) U12.K9@2739.05,847.69 ; v2(2723.3,894.94) U12.J9@2739.05,879.19 ; v2(2723.3,926.43) U12.H9@2739.05,910.69 ; v3(2723.3,957.93) U12.G9@2739.05,942.18 ; U12.N9@2739.05,753.21 v2(2723.3,768.95) U12.M9@2739.05,784.7 ; v2(2754.8,926.43) U12.G10@2770.55,942.18 ; v2(2754.8,1020.92) U12.E10@2770.55,1005.17 ; U12.P10@2770.55,721.71 v3(2786.3,705.96) ; U12.N10@2770.55,753.21 v2(2786.3,737.46) ; U12.M10@2770.55,784.7 v2(2786.3,768.95) ; U12.L10@2770.55,816.2 v2(2786.3,800.45) ; U12.K10@2770.55,847.69 v2(2786.3,831.95) ; U12.J10@2770.55,879.19 v2(2786.3,894.94) ; U12.H10@2770.55,910.69 v2(2786.3,926.43) ; U12.F10@2770.55,973.68 v2(2786.3,957.93) ; U12.N11@2802.05,753.21 v3(2817.79,737.46) ; U12.M11@2802.05,784.7 v2(2817.79,768.95) ; U12.L11@2802.05,816.2 v2(2817.79,800.45) ; U12.K11@2802.05,847.69 v2(2817.79,831.95) ; U12.J11@2802.05,879.19 v2(2817.79,894.94) ; U12.H11@2802.05,910.69 v2(2817.79,926.43) ; U12.G11@2802.05,942.18 v2(2817.79,957.93) ; U12.P12@2833.54,721.71 v2(2849.29,737.46) U12.N12@2833.54,753.21 ; U12.M12@2833.54,784.7 v2(2849.29,768.95) ; U12.L12@2833.54,816.2 v2(2849.29,800.45) ; U12.K12@2833.54,847.69 v3(2849.29,831.95) ; U12.J12@2833.54,879.19 v2(2849.29,894.94) ; U12.H12@2833.54,910.69 v2(2849.29,926.43) ; U12.G12@2833.54,942.18 v3(2849.29,957.93) ; U12.F12@2833.54,973.68 v3(2849.29,989.43) ; U12.E12@2833.54,1005.17 v3(2849.29,1020.92) ; v3(2849.29,674.47) U12.R13@2865.04,690.21 ; U12.P13@2865.04,721.71 v2(2880.79,705.96) ; U12.M13@2865.04,784.7 v3(2880.79,768.95) ; U12.L13@2865.04,816.2 v2(2880.79,800.45) ; U12.J13@2865.04,879.19 v3(2880.79,894.94) ; U12.H13@2865.04,910.69 v2(2880.79,926.43) ; U12.F13@2865.04,973.68 v2(2880.79,989.43) ; U12.E13@2865.04,1005.17 v2(2880.79,1020.92) ; U12.P14@2896.53,721.71 v2(2912.28,705.96) ; U12.M14@2896.53,784.7 v3(2912.28,768.95) ; U12.L14@2896.53,816.2 v3(2912.28,800.45) ; U12.J14@2896.53,879.19 v3(2912.28,863.44) ; U12.H14@2896.53,910.69 v2(2912.28,926.43) ; U12.F14@2896.53,973.68 v3(2912.28,989.43) ; U12.E14@2896.53,1005.17 v3(2912.28,1020.92) ; U12.A18@3022.52,1131.16 3022.52,1171.13 v1(3037.74,1186.35) ; U12.V18@3022.52,595.73 v1(3036.11,582.15) ; U4.A3@3239.65,2287.77 3239.65,2307.29 v1(3251.28,2318.92) ; 3372.63,1510.99 3382.78,1521.15 U20.4@3389.43,1521.15 ; U16.12@3417.54,455.47 3417.54,530.27 U16.25@3447.07,559.8 3476.6,530.27 U16.13@3476.6,455.47 ; v1(4028.11,419.07) 4028.18,419.15 4028.18,437.99 J9.E5@4028.26,438.07
  Top Layer w11.81: v4(3862.94,1866.11) U5.3@3950.54,1866.11
  Top Layer w13.48: 3795.51,1377.79 3795.51,1364.59 3808.49,1351.61 D7.2@3826.84,1351.61 ; v1(4273.17,972.07) Q2.4@4309.04,972.07 ; v1(4352.57,893.36) 4344.79,901.14 4344.79,912.99 4352.69,920.89 Q2.1@4370.2,920.89
  Top Layer w15: v1(-136.83,260.2) R71.1@-104.96,260.2 ; v1(-136.83,360.19) R68.1@-104.96,360.19 ; v1(-136.83,460.2) R64.1@-104.96,460.2 ; v1(-136.83,560.2) R48.1@-104.96,560.2 ; J12.4@465.94,101.41 J12.8@565.94,101.41 ; v1(650.35,530.5) 651.3,531.45 656.33,531.45 700.68,575.8 R73.2@704.62,575.8 ; U1.9@686.23,2569.66 694.28,2561.6 U1.1@694.28,2508.5 694.28,2455.22 689.99,2450.93 ; R2.1@923.09,2499.3 v1(923.09,2536.96) v1@923.09,2537.53 ; v1(1322.26,1277.49) R27.1@1383.27,1277.49 ; v1(1561.83,1643.01) R15.1@1561.83,1583.01 v1(1612.91,1583.01) ; J6.3@1711.54,1978.66 1714.98,1975.22 1764.55,1975.22 1827.47,1912.3 C69.2@1831.41,1912.3 1834.23,1912.3 1838.54,1907.99 U22.3@1838.54,1858.29 ; v1(1714.05,1270.62) U10.3@1714.05,1314.67 ; C26.2@1744.56,1464.17 v1(1744.56,1499.92) ; R18.1@2085.41,1519.96 v1(2085.41,1545.25) ; R6.1@2095.46,2742.71 v1(2095.46,2782.39) ; C36.2@2166.06,1214.65 v1(2195.11,1214.65) ; C35.2@2166.06,1256.14 v1(2195.11,1256.14) ; C38.2@2203.06,1307.14 v1(2242.75,1307.14) ; U7.9@2292.46,1468.98 2367.46,1543.98 U7.4@2446,1543.98 v1(2481.03,1543.98) ; R62.1@2386.96,417.66 2409.94,417.66 2421.11,428.83 v1(2437.94,428.83) ; v1(2427.85,588.19) 2429.2,588.19 2436.74,595.73 U12.V1@2487.08,595.73 U12.U1@2487.08,627.22 ; J15.4@2814.59,72.44 J15.2@2864.59,72.44 ; D5.1@2833.82,1371.13 v1(2833.82,1408.84) ; D6.1@2911.38,1369.16 D6.1@2911.38,1371.13 v1(2911.38,1406.87) ; R8.1@3023.59,2184.26 v1(3063.27,2184.26) ; v1(3166.6,2204.79) C10.2@3166.6,2240.53 ; R51.1@3283.55,1507.07 C68.2@3326.3,1507.06 ; R49.1@3283.55,1632.28 C66.2@3326.3,1632.31 3326.3,1634.28 3341.88,1649.86 3341.88,1660.67 v1(3342.84,1661.63) ; v1(3320.31,1476.38) 3320.31,1477.74 3323.96,1481.38 3323.96,1504.72 C68.2@3326.3,1507.06 ; 3372.63,1510.99 3328.64,1510.99 3326.3,1508.65 C68.2@3326.3,1507.06 ; C12.2@3396.16,2255.19 v1(3396.16,2294.87) ; R13.1@3420.74,1679.17 C20.2@3420.74,1637.65 3422.71,1637.65 3435.54,1624.83 3470.69,1624.83 3473.41,1627.54 3473.41,1653.08 v1(3472.97,1653.52) ; C49.2@3443.48,714.84 v1(3443.48,746.65) ; C41.2@3443.48,1129.49 v1(3443.48,1161.3) ; R43.1@3445.1,820.04 v1(3483.78,820.04) ; C50.1@3552.21,714.84 v1(3552.21,746.65) ; C42.1@3552.21,1129.49 v1(3552.21,1161.3) ; C57.1@3579.54,246.28 v1(3618.22,246.28) ; C56.2@3579.54,301.28 v1(3618.22,301.28) ; v1(3767.94,366.89) C55.2@3767.94,398.7 ; 3795.51,1377.79 3795.51,1390.98 3804.68,1400.15 3804.68,1422.84 C28.2@3812.93,1431.09 v1(3812.93,1465.82) ; v1(3872.39,1203.72) C40.1@3902.2,1203.72 ; v1@3899.84,2384 C70.2@3930.92,2384 ; v1(4074.3,1280.49) U9.19@4115.92,1280.49 ; R37.1@4160.81,1085.17 v1(4160.81,1115.01) ; v1(4217.51,638.34) 4217.9,638.73 4217.9,677.11 R82.1@4218.3,677.5 ; v1(4227.71,877.3) R39.1@4227.71,907.11 ; v1(4242.86,2283.08) 4243.02,2282.93 4272.19,2282.93 Q4.1@4272.35,2282.77 ; v1(4245.31,2453.58) 4246.66,2453.58 4250.13,2450.11 4270.65,2450.11 Q1.1@4271.26,2449.5 ; v1(4253.38,197.24) 4253.38,195.89 4262.61,186.65 4262.61,171.29 C58.2@4270.86,163.04 4262.61,154.79 4262.61,140.05 4253.93,131.38 v1(4253.93,130.02) 4252.97,129.07 4252.97,104.99 C60.2@4251.17,103.18 4252.54,101.81 4252.54,78.6 v1(4253.5,77.64) 4253.5,76.29 4262.61,67.18 4262.61,52.61 C63.2@4270.86,44.37 ; R17.1@4340.33,1530.09 v1(4340.33,1559.1) ; Q1.4@4342.13,2398.32 4342.74,2397.71 4361.64,2397.71 4367.59,2391.77 v1(4368.94,2391.77) ; Q4.4@4343.22,2231.59 4343.83,2230.98 4360.23,2230.98 4370,2221.21 v1(4371.35,2221.21) ; U23.2@4445.67,1098.57 4445.67,1125.96 4450.92,1131.22 v1(4450.92,1132.57) ; U23.2@4446.79,1112.28 U23.2@4447.16,1112.66 ; C71.2@4531.16,533.99 4531.16,446.56 4554.54,423.18 ; v1(4539.82,409.37) 4540.73,409.37 4554.54,423.18 ; U21.5@4604.84,399.28 4604.32,399.8 4577.92,399.8 4554.54,423.18 ; C39.1@4627.71,1049.8 4627.94,1050.02 v1(4665.17,1050.02) ; R21.1@4661.95,1482.23 v1(4689.11,1482.23)
  Top Layer w15.75: U9.23@4115.92,1178.13 4169.07,1178.13 4228.13,1237.19 v4(4228.13,1269.67) U9.25@4228.13,1293.29 ; U9.7@4340.33,1306.09 4287.18,1306.09 4274.39,1293.29 U9.25@4228.13,1293.29 ; U9.8@4340.33,1331.68 4266.51,1331.68 U9.25@4228.13,1293.29 ; U9.11@4340.33,1408.45 4242.67,1408.45 4204.47,1370.24 4204.47,1316.95 U9.25@4228.13,1293.29
  Top Layer w20: J12.8@565.94,101.41 v1(565.94,182.91) ; J12.10@615.94,101.41 v1(615.94,182.91) ; J12.12@665.94,101.41 v1(665.94,182.91) ; J12.16@765.94,101.41 v1(765.94,182.91) ; J12.20@865.94,101.41 v1(865.94,182.91) ; v1(2081.28,-125.61) J14.9@2081.28,-72.63 ; J14.10@2081.28,72.44 v1(2081.28,125.42) ; C47.2@2110.99,798.9 2110.99,837.61 ; v1(2131.28,-125.61) J14.7@2131.28,-72.63 ; J14.8@2131.28,72.44 v1(2131.28,125.42) ; v1(2206.92,439.22) C54.2@2241.66,439.22 v1(2241.66,404.47) ; Y1.2@2338.24,601.63 v1(2372.99,601.63) ; J15.16@2514.59,72.44 v1(2514.59,125.42) ; v1(3482.19,54.91) J13.4@3482.19,111.13 ; v1(3532.19,54.91) J13.2@3532.19,111.13 ; v1(3836.01,123.11) J9.A13@3870.78,123.11 ; v1(3836.01,516.81) J9.A3@3870.78,516.81 ; v1@3949.32,182.07 3949.32,167.24 3949.52,167.04 J9.C12@3949.52,162.48 ; v1(3950.54,1646.02) C21.2@3950.54,1682.72 ; v1(4022.96,946.48) U14.3@4060.65,946.48 ; v1@4027.74,182.03 4027.74,162.99 J9.E12@4028.26,162.48 ; v1(4033.36,1716.87) C18.2@4033.36,1753.57 ; v1(4067.33,181.73) 4067.33,162.77 J9.F12@4067.63,162.48 ; J9.G12@4107,162.48 v1(4141.76,162.48) ; J9.G4@4107,477.44 v1(4141.76,477.44) ; C25.1@4115.92,1544.77 v1(4115.92,1578.52) ; v1(4217.51,395.27) C53.2@4217.51,431.02 ; C52.2@4217.51,602.59 v1(4217.51,638.34) ; C24.2@4608.12,1569.44 v1(4648.77,1569.44)
  GND1 w15: -139.12,-139.12 H3.1@0,0 ; -139.12,139.12 H3.1@0,0 ; -139.12,2598.33 H1.1@0,2737.45 ; -139.12,2876.57 H1.1@0,2737.45 ; 139.12,-139.12 H3.1@0,0 ; 139.12,139.12 H3.1@0,0 ; 139.12,2598.33 H1.1@0,2737.45 ; 139.12,2876.57 H1.1@0,2737.45 ; 4388.88,-139.12 H4.1@4528,0 ; 4388.88,139.12 H4.1@4528,0 ; 4388.88,2598.33 H2.1@4528,2737.45 ; 4388.88,2876.57 H2.1@4528,2737.45 ; 4667.12,-139.12 H4.1@4528,0 ; 4667.12,139.12 H4.1@4528,0 ; 4667.12,2598.33 H2.1@4528,2737.45 ; 4667.12,2876.57 H2.1@4528,2737.45
  GND2 w15: -139.12,-139.12 H3.1@0,0 ; -139.12,139.12 H3.1@0,0 ; -139.12,2598.33 H1.1@0,2737.45 ; -139.12,2876.57 H1.1@0,2737.45 ; 139.12,-139.12 H3.1@0,0 ; 139.12,139.12 H3.1@0,0 ; 139.12,2598.33 H1.1@0,2737.45 ; 139.12,2876.57 H1.1@0,2737.45 ; 4388.88,-139.12 H4.1@4528,0 ; 4388.88,139.12 H4.1@4528,0 ; 4388.88,2598.33 H2.1@4528,2737.45 ; 4388.88,2876.57 H2.1@4528,2737.45 ; 4667.12,-139.12 H4.1@4528,0 ; 4667.12,139.12 H4.1@4528,0 ; 4667.12,2598.33 H2.1@4528,2737.45 ; 4667.12,2876.57 H2.1@4528,2737.45
  Bottom Layer w10: 1427.14,779.09 1454.77,779.09 1482.39,779.09 ; 1581.86,779.09 1609.49,779.09 1637.11,779.09 ; C508.2@2871.13,1074.92 2898.86,1074.92 2904.72,1069.06 2904.72,1044.85 v2(2880.79,1020.92) ; v2(2912.28,705.96) 2912.28,704.34 2917.79,698.83 C550.2@2917.79,674.47 ; C530.2@3003.76,863.44 3006.77,860.43 v2(3006.77,831.95)
  Bottom Layer w12: C545.2@2518.56,711.16 2518.56,690.24 v3(2534.33,674.47)
  Bottom Layer w13: v1(495.23,223.86) C556.2@495.23,255.67 ; v1(665.94,182.91) v1@667.24,184.2 ; v1(688.19,223.86) C557.1@688.19,255.67
  Bottom Layer w14.5: v1(1785.4,1641.21) C501.2@1823.27,1641.21
  Bottom Layer w15: C555.2@608.54,530.5 v1(650.35,530.5) ; R500.1@844.28,2555.74 855.4,2566.86 v1(855.4,2613.27) ; v1(1416.04,1438.25) 1458.68,1438.25 C503.2@1462.92,1434.01 ; v1(1472.46,713.99) 1486.61,699.84 C544.2@1517.81,699.84 ; C506.2@1490.93,1259.59 v1(1490.93,1298.41) ; C526.2@1579.7,898.21 v1(1579.7,937.64) ; C525.2@2534.33,952.42 C524.2@2565.82,952.42 2565.82,977.91 2573.99,986.08 C519.2@2597.32,986.08 ; C529.2@2597.21,876.55 2597.21,894.83 v2(2597.32,894.94) ; C528.2@2628.82,876.43 v2(2628.82,894.94) ; v3(2691.81,705.96) 2694.56,703.21 C547.2@2729.62,703.21 ; v2(2754.8,1020.92) 2754.8,1046.91 2758.76,1050.86 2758.76,1051.65 2759.53,1052.42 C509.2@2760.31,1052.42 ; v3(2912.28,768.95) 2915.04,766.2 C537.2@2943.78,766.2 ; C504.2@3878.72,1381.14 v1(3878.72,1414.89) ; v1(3927.75,1281.53) C505.2@3961.5,1281.53 ; v1(4087.69,1085.17) C507.2@4121.44,1085.17 ; v1(4560.47,2528.15) 4560.47,2468.52 J2.7@4560.98,2468.02 ; v1(4560.9,1996.57) 4560.9,2050.62 J2.8@4560.98,2050.7
  Bottom Layer w15.75: C520.2@2760.38,959.53 2784.63,959.53 2786.23,957.93 v2(2786.3,957.93)
  Bottom Layer w20: v1(2427.85,588.19) C554.2@2427.85,622.93
  other v1: 1.48,-103.95 4529.48,-103.95 -72.46,-74.55 4455.54,-74.55 74.55,-72.46 4602.55,-72.46 -103.95,-1.48 4424.05,-1.48 103.95,1.48 4631.95,1.48 3662.97,44.97 2904.27,46.47 -74.55,72.46 4453.45,72.46 72.46,74.55 4600.46,74.55 2904.27,96.47 -1.48,103.95 4526.52,103.95 3662.97,116.09 3949.32,181.73 4027.74,181.73 3662.97,187.22 479.04,550.44 525.76,550.44 479.04,606.55 478.55,662.66 2155.9,812.06 2079.02,858.52 2117.46,858.52 2155.9,858.52 4388.53,893.36 4424.5,893.36 2141.39,930.36 2141.39,999.59 2141.39,1068.81 2141.39,1138.04 2682.1,1434.37 2612.34,1434.6 2751.58,1434.54 3763.01,1592.79 3763.01,1638.8 3763.01,1684.82 795.53,1784.16 891.81,1784.16 988.09,1784.16 795.53,1880.44 891.81,1880.44 988.09,1880.44 4573.44,1915.29 4620.62,1915.29 4667.8,1915.29 3873.81,1986.96 531.25,1992.3 627.53,1992.3 723.8,1992.3 820.08,1992.3 916.35,1992.3 3873.81,2035.54 3873.81,2084.11 531.25,2088.58 627.53,2088.58 723.8,2088.58 820.08,2088.58 916.35,2088.58 1922.97,2153.4 2708.19,2216.59 2930.47,2254.96 1947.7,2282.05 2930.47,2288.34 2318.8,2294.96 2683.46,2297.29 2347.55,2351.08 636.14,2355.96 3899.23,2383.39 2318.8,2405.06 637.74,2459.9 637.74,2525.6 593.03,2591.31 637.74,2591.31 1.48,2633.5 4529.48,2633.5 593.03,2650 637.74,2650 -72.46,2662.9 4455.54,2662.9 74.55,2664.99 4602.55,2664.99 -103.95,2735.97 4424.05,2735.97 103.95,2738.93 4631.95,2738.93 -74.55,2809.91 4453.45,2809.91 72.46,2812 4600.46,2812 -1.48,2841.4 4526.52,2841.4
  other v4: 587.58,331.72 587.58,371.09 3447.07,485 3416.56,559.8 3477.58,559.8 3447.07,634.6 3447.07,902.49 3416.56,977.29 3477.58,977.29 3447.07,1052.09 4188.76,1222.42 4228.13,1222.42 4267.5,1222.42 4188.76,1269.67 4267.5,1269.67 4188.76,1316.91 4228.13,1316.91 4267.5,1316.91 4188.76,1364.16 4228.13,1364.16 4267.5,1364.16 3845.23,1839.54 3880.66,1839.54 3845.23,1892.69 3880.66,1892.69 1826.33,2386.62 1872.79,2386.62 2567.16,2386.62 2613.62,2386.62 1826.33,2433.08 1872.79,2433.08 2567.16,2433.08 2613.62,2433.08
  other v5: 3910.15,83.74 4067.63,83.74 3949.52,123.11 3988.89,123.11 3943.18,484.5 4028.26,516.81
  other v6: 718.1,2596.09 769.28,2596.09 820.46,2596.09 718.1,2647.27 769.28,2647.27 820.46,2647.27
  other v7: 4188.76,1175.18 4228.13,1175.18 4267.5,1175.18 4188.76,1411.4 4228.13,1411.4 4267.5,1411.4
GPMC_AD0: J13.5 U12.K4 | length 2244.9
  Top Layer w6.5: v2(2565.78,863.14) U12.K4@2581.53,847.39 ; v1(3432.19,-167.54) J13.5@3432.19,-111.32
  SIGNAL1 w6.5: v2@2567.06,863.44 2518.57,911.93 2419.78,911.93 2336.74,828.89 2336.74,640.95 2300.3,604.52 2300.3,363.61 2477.1,186.8 2477.1,113.56 2682.22,-91.56 2823.87,-91.56 2842.84,-110.53 2842.84,-121.53 2888.84,-167.54 v1(3432.19,-167.54)
GPMC_AD1: J13.7 U12.K3 | length 2237
  Top Layer w6.5: v2(2534.33,831.95) U12.K3@2550.08,847.69 ; J13.7@3382.19,-111.32 v1(3382.19,-55.1)
  SIGNAL1 w6.5: v2(2534.33,831.95) 2534.33,842.2 2512.19,864.34 2501.93,864.34 2472.52,893.75 2440.47,893.75 2424.3,893.75 2359.17,828.62 2359.17,639.11 2316.7,596.64 2316.7,371.25 2544.41,143.54 2544.41,74.76 2570.38,48.79 2637.64,48.79 2720.72,-34.29 2852.2,-34.29 2863.64,-45.73 2863.64,-121.17 2891.1,-148.62 3366.85,-148.62 3382.19,-133.29 v1(3382.19,-55.1)
GPMC_AD2: J13.9 U12.V17 | length 2129.9
  Top Layer w6.5: U12.V17@2991.02,595.73 2991.02,583.26 3014.66,559.63 v1(3094.92,559.63) ; J13.9@3332.19,-111.32 v1(3332.19,-55.1)
  SIGNAL2 w6.5: v1(3094.92,559.63) 3145.87,559.63 3182.38,523.12 3248.28,523.12 3252.51,518.89 3252.51,501.92 3247.52,496.93 3119.93,496.93 3116.12,493.12 3116.12,476.14 3121.11,471.15 3260.7,471.15 3264.51,467.35 3264.51,450.37 3259.52,445.38 3119.93,445.38 3116.12,441.57 3116.12,423.42 3119.93,419.61 3260.7,419.61 3264.51,415.8 3264.51,398.83 3259.52,393.84 3119.93,393.84 3116.12,390.03 3116.12,370.82 3119.93,367.01 3260.7,367.01 3264.51,363.21 3264.51,342.03 3260.7,338.22 3122.65,338.22 3102.71,318.27 3102.71,242.06 3160.93,183.83 3160.93,141.2 3138.67,118.93 3138.67,-13.32 3151.8,-26.46 3283.89,-26.46 3312.53,-55.1 v1(3332.19,-55.1)
GPMC_AD3: J13.11 U12.T16 | length 2115.8
  Top Layer w6.5: U12.T16@2959.53,658.72 v2(2975.27,642.97) ; J13.11@3282.19,-111.32 v1(3282.19,-55.1)
  SIGNAL2 w5: v2(2975.27,642.97) 2990.77,658.47 3014.69,658.47
  SIGNAL2 w6.5: 3014.69,658.47 3024.57,658.47 3063.43,619.61 3063.43,553.01 3048.87,538.45 3048.87,411.35 3028.68,391.16 3028.68,162.02 3034.7,156.01 3100.6,156.01 3104.83,151.77 3104.83,134.8 3099.84,129.81 2991.25,129.81 2987.45,126 2987.45,109.03 2992.44,104.04 3101.02,104.04 3104.83,100.23 3104.83,83.26 3099.84,78.27 2991.25,78.27 2987.45,74.46 2987.45,56.3 2991.25,52.49 3101.02,52.49 3104.83,48.69 3104.83,31.71 3099.84,26.72 2991.25,26.72 2987.45,22.92 2987.45,3.71 2991.25,-0.1 3101.02,-0.1 3104.83,-3.91 3104.83,-20.88 3101.02,-24.69 3006.98,-24.69 3003.17,-28.5 3003.17,-108.28 3021.14,-126.26 3255.93,-126.26 3282.19,-99.99 v1(3282.19,-55.1)
GPMC_AD4: J13.13 U12.P15 | length 2233.4
  Top Layer w6.5: U12.P15@2928.03,721.71 v2(2943.78,705.96) ; J13.13@3232.19,-111.32 v1(3232.19,-55.1)
  SIGNAL1 w5: v2(2943.78,705.96) 2959.72,721.91 2981.64,721.91 2990.62,730.89
  SIGNAL1 w6.5: 2990.62,730.89 2999.6,739.86 3023.09,739.86 3041.68,721.28 3041.68,678.49 3193.21,526.95 3193.21,424.09 3200.23,417.07 3343.86,417.07 3348.77,412.16 3348.77,384.8 3343.78,379.81 3200.69,379.81 3196.89,376.01 3196.89,359.03 3201.88,354.04 3344.97,354.04 3348.77,350.23 3348.77,333.26 3343.78,328.27 3280.69,328.27 3276.89,324.46 3276.89,307.49 3281.88,302.5 3344.97,302.5 3348.77,298.69 3348.77,281.72 3343.78,276.73 3280.69,276.73 3276.89,272.92 3276.89,255.95 3281.88,250.96 3344.97,250.95 3348.77,247.15 3348.77,227.56 3343.77,222.56 3279.59,222.56 3257.03,200 3195.38,200 3186.82,191.44 3186.82,153.12 3195.21,144.73 3214.35,144.73 3232.19,126.88 3232.19,112.4 3237.28,107.31 3286.37,107.31 3290.18,103.5 3290.18,86.52 3285.19,81.53 3236.1,81.53 3232.29,77.73 3232.29,60.75 3237.28,55.76 3286.37,55.76 3290.18,51.95 3290.18,34.98 3285.19,29.99 3236.1,29.99 3232.29,26.18 3232.29,9.21 3237.28,4.22 3286.37,4.22 3290.18,0.41 3290.18,-16.56 3285.19,-21.55 3236.1,-21.55 3232.29,-25.36 v1@3232.29,-55
GPMC_AD5: J13.15 U12.R16 | length 2251.6
  Top Layer w6.5: U12.R16@2959.28,690.21 v2(2975.03,705.96) ; J13.15@3182.19,-111.32 v1(3182.19,-55.1)
  SIGNAL1 w6.5: v2(2975.03,705.96) 2983.79,705.96 3000.04,722.21 3014.31,722.21 3030.18,706.35 3030.18,658.9 3159.9,529.18 3159.9,505 3154.83,499.93 3085.76,499.93 3080.77,494.94 3080.77,477.97 3084.58,474.16 3175.03,474.16 3178.84,470.35 3178.84,453.38 3173.85,448.39 3105.76,448.39 3100.77,443.4 3100.77,426.43 3104.58,422.62 3172.66,422.62 3177.66,417.63 3177.66,400.66 3173.85,396.85 3078.76,396.85 3073.77,391.86 3073.77,374.88 3077.58,371.08 3172.66,371.08 3177.66,366.08 3177.66,349.11 3173.85,345.3 3078.76,345.3 3073.77,340.31 3073.77,323.34 3077.58,319.53 3172.66,319.53 3177.66,314.54 3177.66,297.57 3173.85,293.76 3050.76,293.76 3045.77,288.77 3045.77,271.8 3049.58,267.99 3172.66,267.99 3177.66,263 3177.66,246.03 3173.85,242.22 3050.76,242.22 3046.95,238.41 3046.95,221.44 3050.76,217.63 3164.06,217.63 3171.11,210.59 3171.11,108.71 3212.74,67.08 3212.74,39.83 3199.04,26.13 3165.14,26.13 3152.32,13.31 3152.32,-45.28 3162.13,-55.1 v1(3182.19,-55.1)
GPMC_AD6: J13.17 U12.L3 | length 2248.9
  Top Layer w6.5: v2(2534.33,800.45) U12.L3@2550.08,816.2 ; J13.17@3132.19,-111.32 v1(3132.19,-55.1)
  SIGNAL1 w5: v2(2534.33,800.45) 2550.32,784.46 2550.32,732.53
  SIGNAL1 w6.5: 2550.32,732.53 2550.32,722.76 2546.51,718.95 2480.71,718.95 2472.1,710.34 2472.1,647.49 2525.62,593.97 2726.18,593.97 2732.03,588.13 2732.03,546.91 2732.03,413.08 2690.84,371.89 2676.98,371.89 2650.33,345.25 2650.33,329.44 2622.31,301.41 2622.31,205.4 2701.39,126.32 2934.19,126.32 2954.57,105.94 2967.25,105.94 3023.31,162.01 3028.7,162.01 3040.7,150 3040.7,142.95 2983.83,86.07 2983.83,80.69 2995.83,68.69 3002.89,68.69 3057.84,123.64 3063.22,123.64 3075.22,111.63 3075.22,104.58 3020.79,50.14 3020.79,44.75 3032.79,32.75 3039.85,32.75 3096.03,88.94 3101.42,88.94 3113.42,76.93 3113.42,69.88 3058.98,15.44 3058.98,10.05 3070.98,-1.95 3078.04,-1.95 3119.78,39.79 3125.16,39.79 3137.17,27.79 3137.17,20.73 3108.93,-7.5 3108.93,-31.84 v1(3132.19,-55.1)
